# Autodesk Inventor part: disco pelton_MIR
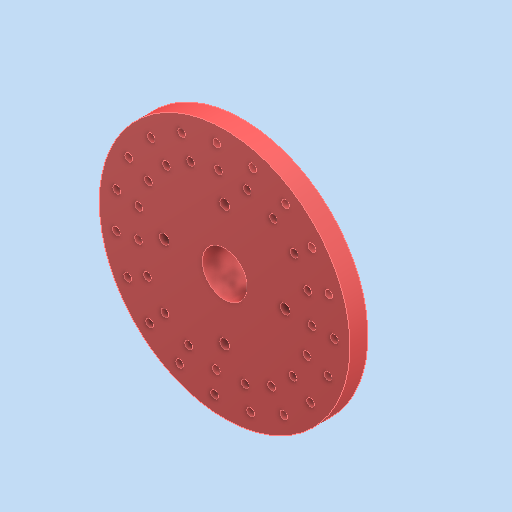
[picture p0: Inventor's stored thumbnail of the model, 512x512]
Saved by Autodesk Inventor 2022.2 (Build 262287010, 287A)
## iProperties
Created: 2025-03
Part Number: disco pelton_MIR
Material: Plastica ABS
Document SubType Name: Modeling
Designer: 18907419
Density: 1.06 g/cm^3
Appearance: Default
Author: 18907419
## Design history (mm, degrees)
feature "Solido1"
node "Solido2"
